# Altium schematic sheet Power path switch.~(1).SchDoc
size A3; SheetNumber: 6; SheetTotal: 6
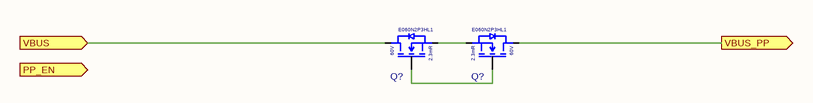
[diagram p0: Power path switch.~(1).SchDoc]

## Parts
(Parts that share a designator on the sheet are numbered #1, #2 ... from top to bottom, then left to right.)
Q?#1  Rds: 2.3mR  Voltage: 60V  [DFN-8 (5x6)]  (hidden comment: E060N2P3HL1)
Q?#2  Rds: 2.3mR  Voltage: 60V  [DFN-8 (5x6)]  (hidden comment: E060N2P3HL1)

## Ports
PP_EN (in, see Arhitecture[4A]), VBUS (in, see Arhitecture[3A]), VBUS_PP (out, see Arhitecture[4A])

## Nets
VBUS: Q?#1.D ; port VBUS
VBUS_PP: Q?#2.D ; port VBUS_PP
NetQ?#1_G: Q?#1.G Q?#2.G
NetQ?#1_S: Q?#1.S Q?#2.S

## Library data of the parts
Q?#1 Q?#2 = E060N2P3HL1: Nmos 60V 180A 2.3mR PDFN5x6-8; Manufacturer: Existar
